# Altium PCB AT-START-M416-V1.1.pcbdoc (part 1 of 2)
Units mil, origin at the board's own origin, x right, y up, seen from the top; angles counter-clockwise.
Board outline 4292.45 x 3617.4 mil, 2 copper layers (Top Layer, Bottom Layer); 119 components, 108 nets, 464 pads, 671 vias.
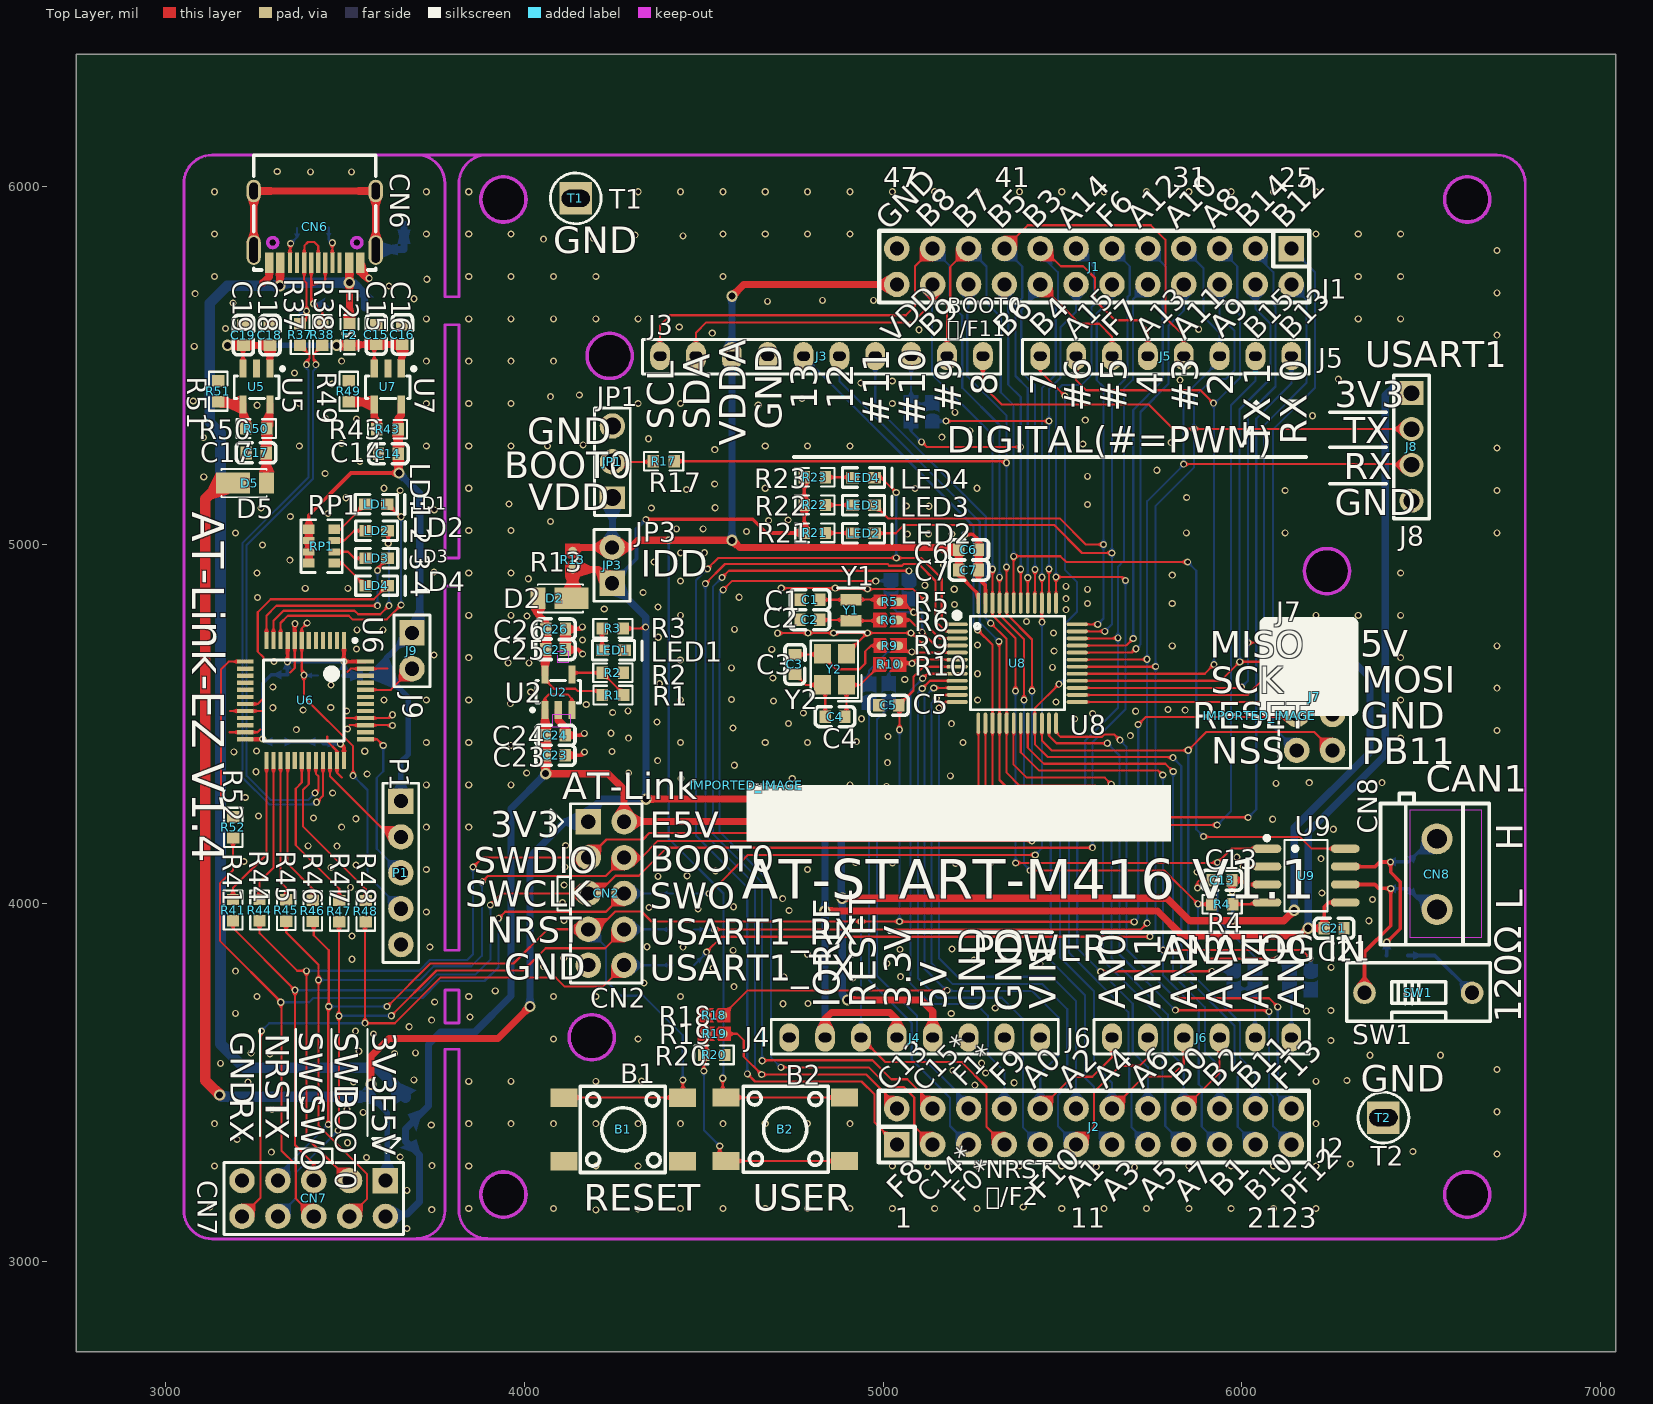
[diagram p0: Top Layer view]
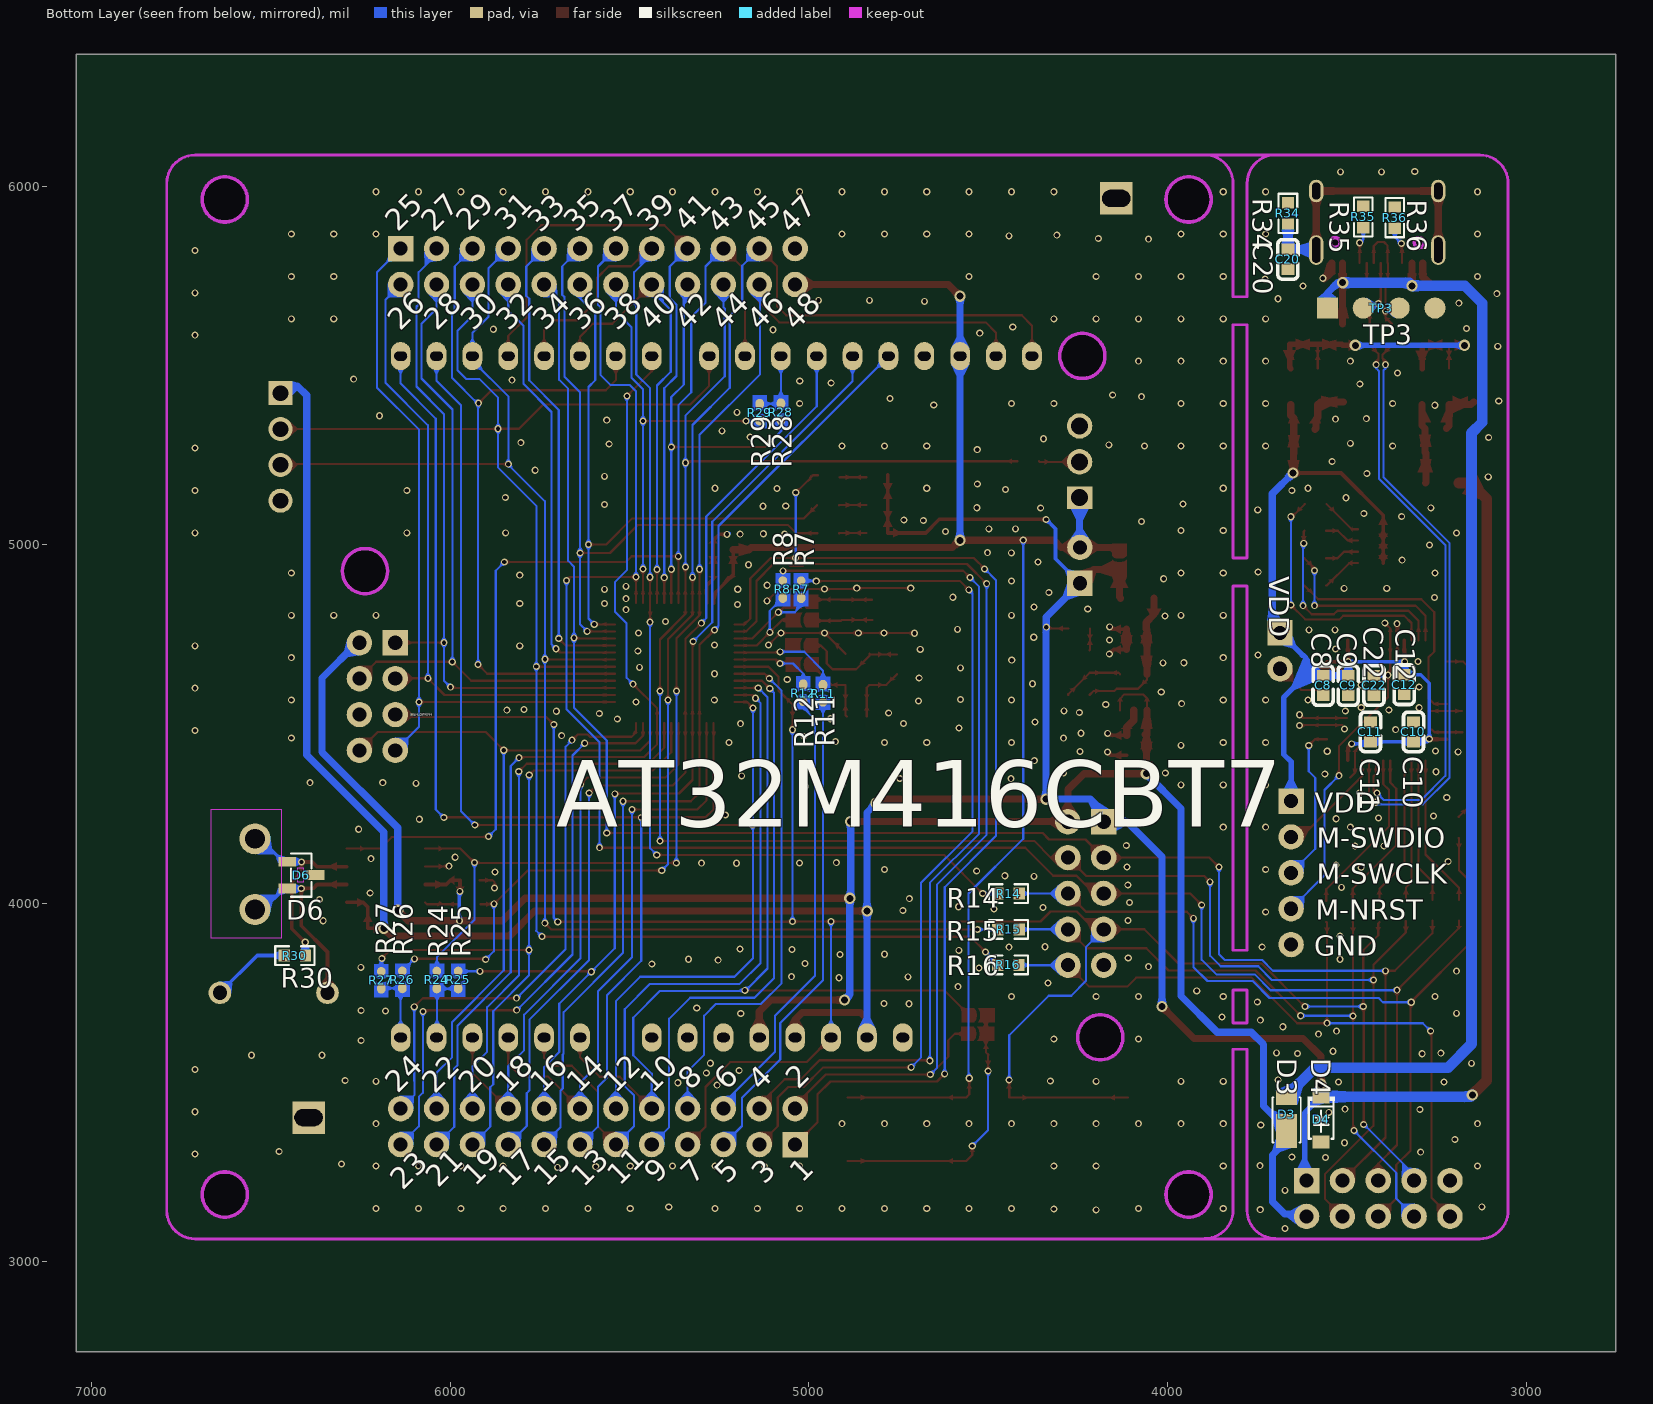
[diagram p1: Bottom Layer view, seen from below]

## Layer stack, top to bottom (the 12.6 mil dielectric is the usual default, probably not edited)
Top Layer: signal copper (thickness not stored)
Dielectric: dielectric 12.6, FR-4, Dk 4.8
Bottom Layer: signal copper (thickness not stored)

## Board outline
7042.45,2750 2750,2750 2750,6367.4 7042.45,6367.4
cut-out: 6691.34,5962.67 ccw(c6628.34,5962.67) 6565.35,5962.67 ccw(c6628.34,5962.67)
cut-out: 6691.34,3187.98 ccw(c6628.34,3187.98) 6565.35,3187.98 ccw(c6628.34,3187.98)
cut-out: 4003.92,3187.98 ccw(c3940.92,3187.98) 3877.93,3187.98 ccw(c3940.92,3187.98)
cut-out: 4250.26,3626.35 ccw(c4187.26,3626.35) 4124.27,3626.35 ccw(c4187.26,3626.35)
cut-out: 6300.26,4926.35 ccw(c6237.27,4925.79) 6174.28,4926.35 ccw(c6237.27,4926.91)
cut-out: 4300.26,5526.35 ccw(c4237.26,5526.35) 4174.27,5526.35 ccw(c4237.26,5526.35)
cut-out: 4003.93,5962.67 ccw(c3940.94,5962.44) 3877.95,5962.67 ccw(c3940.94,5962.89)

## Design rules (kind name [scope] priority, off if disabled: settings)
BoardOutlineClearance copperThickness1oz [All] p0: genericclearance=10 ignorepadtopadclearanceinfootprint=FALSE except(0: Arc-SplitContinuation Track-SplitContinuation SMDPad-SplitContinuation THPad-SplitContinuation Via-SplitContinuation Fill-SplitContinuation Poly-SplitContinuation Region-SplitContinuation Text-SplitContinuation; 6: SMDPad-CutoutEdge THPad-CutoutEdge Via-CutoutEdge Fill-CutoutEdge Region-CutoutEdge; 11.8: Track-OutlineEdge SMDPad-OutlineEdge THPad-OutlineEdge Via-OutlineEdge Fill-OutlineEdge Region-OutlineEdge Poly-OutlineEdge Text-OutlineEdge Track-CutoutEdge)
Clearance copperThickness1oz [(InNet('3V3') OR InNet('PA15') OR InNet('VCC') OR InNet('M-NRST') OR InNet('M-USB_DM') OR InNet('ATLINK_5V') OR InNet('M-USB_DP') OR InNet('USBP') OR InNet('USBM') OR InNet('GND') OR InNet('PB13') OR InNet('PC13') OR InNet('PB12') OR InNet('PB14') OR InNet('PB15') OR InNet('PB6') OR InNet('PB11') OR InNet('PB2') OR InNet('PB1') OR InNet('PF7') OR InNet('PF6') OR InNet('VDD') OR InNet('LD4') OR InNet('ATLK_RX') OR InNet('ATLK_TX') OR InNet('PF1') OR InNet('PF0') OR InNet('PC15') OR InNet('PC14') OR InNet('LD1') OR InNet('LD2') OR InNet('LD3') OR InNet('ATLK_SWCLK') OR InNet('ATLK_SWDIO') OR InNet('ATLK_BOOT0') OR InNet('ATLK_NRST') OR InNet('M-ATLK_TX') OR InNet('M-ATLK_RX') OR InNet('M-SWCLK') OR InNet('M-BOOT0') OR InNet('M-SWDIO') OR InNet('VCC3.5V') OR InNet('PA12') OR InNet('PA11') OR InNet('ATLK_SWO') OR InNet('$1N792') OR InNet('$1N793') OR InNet('$1N794') OR InNet('$1N795') OR InNet('$2N438') OR InNet('$3N526') OR InNet('$1N16959') OR InNet('PA14/SWCLK') OR InNet('PA13/SWDIO') OR InNet('PF11/BOOT0') OR InNet('NRST/PF2') OR InNet('PB3') OR InNet('$1N17598') OR InNet('$1N17675') OR InNet('$2N5975') OR InNet('$2N6210') OR InNet('$2N6248') OR InNet('$2N6104') OR InNet('$2N6111') OR InNet('$2N5937') OR InNet('$2N5955') OR InNet('$3N7356') OR InNet('$3N6624') OR InNet('$3N6989') OR InNet('$3N7005') OR InNet('$3N7010') OR InNet('$3N7265') OR InNet('PA0') OR InNet('$4N2984') OR InNet('$4N3391') OR InNet('$4N3469') OR InNet('PA6') OR InNet('E5V') OR InNet('PA9/USART1_TX') OR InNet('PA10/USART1_RX') OR InNet('PF8') OR InNet('PB10') OR InNet('PA8') OR InNet('PB4') OR InNet('PB5') OR InNet('PA2') OR InNet('PA3') OR InNet('PB0') OR InNet('PA4') OR InNet('PA1') OR InNet('PA5') OR InNet('PA7') OR InNet('PF10') OR InNet('PF9') OR InNet('PF12') OR InNet('PF13') OR InNet('CC2') OR InNet('CC1') OR InNet('EGND') OR InNet('$2N7510') OR InNet('SWO') OR InNet('CAN1_RX') OR InNet('CAN1_TX') OR InNet('CAN1_STB') OR InNet('CAN_L') OR InNet('CAN_H') OR InNet('$3N14088') OR InNet('$3N14090'))] p1: gap=7 ignorepadtopadclearanceinfootprint=FALSE except(6: Track-Track Track-SMDPad SMDPad-SMDPad Track-THPad SMDPad-THPad THPad-THPad Track-Via SMDPad-Via THPad-Via Via-Via Track-Fill SMDPad-Fill THPad-Fill Via-Fill Fill-Fill SMDPad-Region THPad-Region Via-Region Fill-Region Region-Region Track-Poly SMDPad-Poly THPad-Poly Via-Poly Fill-Poly Poly-Poly Track-Text SMDPad-Text THPad-Text Via-Text Fill-Text Region-Text Poly-Text Text-Text Track-Hole SMDPad-Hole THPad-Hole Via-Hole Fill-Hole Region-Hole Poly-Hole Text-Hole; 11.8: Track-Region Region-Poly Track-Sheet SMDPad-Sheet THPad-Sheet Via-Sheet Fill-Sheet Region-Sheet Poly-Sheet Text-Sheet Sheet-Hole)
DiffPairsRouting differentialPair [All] p1: maxuncoupledlength=10 minlimit=6 maxlimit=6 mostfreqgap=6 toplayer_minwidth=5 toplayer_prefwidth=10 toplayer_maxwidth=100 bottomlayer_minwidth=5 bottomlayer_prefwidth=10 bottomlayer_maxwidth=100
PasteMaskExpansion pasteMaskExpansion [All] p1: expansion=0
PlaneConnect innerPlane [All] p1: planeconnectstyle=Relief reliefexpansion=20 reliefentries=4 reliefconductorwidth=10 reliefairgap=10
PolygonConnect copperRegion [All] p1: connectstyle=Relief reliefentries=4 reliefconductorwidth=10 polygonreliefangle="90 Angle" airgapwidth=10
RoutingVias viaSize [All] p1: viastyle="Through Hole" holewidth=11.8 minholewidth=11.8 maxholewidth=27.6 width=19.7 minwidth=19.7 maxwidth=39.4
SolderMaskExpansion solderMaskExpansion [All] p1: useseparateexpansions=TRUE expansion=2 expansionbottom=2
Width copperThickness1oz [All] p1: maxlimit=100 minlimit=5 preferedwidth=6

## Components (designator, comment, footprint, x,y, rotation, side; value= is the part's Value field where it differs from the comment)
B1 "TS-1002S-05026C" KEY-SMD_4P-L6.0-W6.0-P4.50-LS9.0 4275.36,3369.64 r0 top
B2 "TSA063G60-250" KEY-SMD_4P-L6.1-W6.1-P4.50-LS9.0 4726.55,3369.99 r180 top
C1 "CL10C180JB8NNNC" C0603 4796.08,4846.54 r0 top
C2 "CL10C180JB8NNNC" C0603 4795.58,4790.46 r0 top
C3 "CL10C150JB8NNNC" C0603 4753.97,4666.49 r90 top
C4 "CL10C150JB8NNNC" C0603 4865.97,4520.49 r0 top
C5 "CC0603KRX7R9BB104" C0603 5015.49,4552.03 r0 top
C6 "CL10A475KO8NNNC" C0603 5238.29,4985.83 r180 top
C7 "CC0603KRX7R9BB104" C0603 5238.35,4929.24 r180 top
C8 "CL10A475KO8NNNC" C0603 3565.92,4607.82 r90 bottom
C9 "CC0603KRX7R9BB104" C0603 3495.92,4607.82 r90 bottom
C10 "CC0603KRX7R9BB104" C0603 3313.92,4477.82 r270 bottom
C11 "CC0603KRX7R9BB104" C0603 3433.92,4477.82 r270 bottom
C12 "CC0603KRX7R9BB104" C0603 3339.92,4609.82 r90 bottom
C13 "CC0603KRX7R9BB104" C0603 5944.97,4064.49 r0 top
C14 "CL10A106KP8NNNC" C0603 3620.53,5253.61 r0 top
C15 "CL10A106KP8NNNC" C0603 3586.1,5585.92 r270 top
C16 "CC0603KRX7R9BB104" C0603 3659.3,5585.96 r270 top
C17 "CL10A106KP8NNNC" C0603 3251.92,5255.82 r0 top
C18 "CL10A106KP8NNNC" C0603 3290.1,5583.92 r270 top
C19 "CC0603KRX7R9BB104" C0603 3216.1,5583.92 r270 top
C20 "CC0603KRX7R9BB104" C0603 3663.92,5795.82 r90 bottom
C21 "CC0603KRX7R9BB104" C0603 6256.97,3930.49 r180 top
C22 "CC0603KRX7R9BB104" C0603 3423.92,4607.82 r90 bottom
C23 "CL10A106KP8NNNC" C0603 4085.97,4412.49 r0 top
C24 "CC0603KRX7R9BB104" C0603 4085.97,4468.49 r0 top
C25 "CL10A106KP8NNNC" C0603 4086.25,4707.66 r0 top
C26 "CC0603KRX7R9BB104" C0603 4086.58,4764.74 r0 top
CN2 "CON10" HDR2X5 4177.67,4227.53 r270 top
CN6 "TYPEC-304-BCP16" USB-C-SMD_TYPEC-304-BCP16 3414.92,5885.82 r180 top
CN7 "CON10" HDR2X5 3612.1,3227.03 r180 top
CN8 "KF301-5.0-2P" CONN-TH_P5.00_KF301-5.0-2P 6543.97,4081.49 r90 top
D2 "DFLS130L-7" POWERDI-123_L2.8-W1.8-LS3.7-RD 4083.97,4850.49 r180 top
D3 "DFLS130L-7" POWERDI-123_L2.8-W1.8-LS3.7-RD 3667.92,3411.82 r90 bottom
D4 "SMF3.3A_C2759873" SOD-123FL_L2.8-W1.8-LS3.8-RD 3571.62,3397.74 r270 bottom
D5 "DFLS130L-7" POWERDI-123_L2.8-W1.8-LS3.7-RD 3233.92,5171.82 r0 top
D6 "PESD2CANFD24V-TR" SOT-23-3_L2.9-W1.3-P1.90-LS2.4-BR 6414.97,4078.49 r0 bottom
F2 "BSMD0603-050-6V" F0603 3511.92,5585.82 r270 top
IMPORTED_IMAGE "IMPORTED_IMAGE" IMPORTED_IMAGE 6049.2,4522.45 r0 top
IMPORTED_IMAGE "IMPORTED_IMAGE" IMPORTED_IMAGE 4619.97,4329.49 r0 top
J1 "Header 12X2" HEAD2*12 6137.91,5825.49 r180 top
J2 "Header 12X2" HEAD2*12 5037.93,3327.39 r0 top
J3 "CON10" "HDR1X10 - 2#" 5277.93,5525.82 r180 top
J4 "CON8" "HDR1X8 - 2#" 4737.93,3625.82 r0 top
J5 "CON8" "HDR1X8 - 2#" 6137.93,5525.82 r180 top
J6 "CON6" "HDR1X6 -2#" 5637.93,3625.82 r0 top
J7 "Header 4X2" HDR2X4 6152.93,4726.39 r270 top
J8 "PZ2.54-1*4-WZ" HDR-TH_4P-P2.54-H-M-W7.7-P 6473.03,5272.49 r270 top
J9 "1X2P_2.54M" HDR1X2 3686.1,4754.03 r270 top
JP1 "2.54-1*3P针" HDR-TH_3P-P2.54-V-M-1 4244.82,5230.95 r90 top
JP3 "1X2P_2.54M" HDR1X2 4243.97,4892.49 r90 top
LD1 "RED" LED0603 3556.14,5112.82 r0 top
LD2 "GREEN" LED0603 3557.1,5038.72 r0 top
LD3 "BLUE" LED0603 3557.14,4961.82 r0 top
LD4 "YELLOW" LED0603 3557.1,4885.82 r0 top
LED1 "RED" LED0603 4217.22,4705.31 r0 top
LED2 "RED" LED0603 4914.8,5031.55 r0 top
LED3 "YELLOW" LED0603 4914.43,5109.54 r0 top
LED4 "GREEN" LED0603 4914.61,5187.03 r0 top
P1 "Header 5" HDR1X5 3655.1,4285.03 r270 top
R1 "0603WAF5102T5E" R0603 4246.78,4580.68 r0 top
R2 "0603WAF1502T5E" R0603 4246.14,4642.98 r0 top
R3 "0603WAF1001T5E" R0603 4245.97,4766.49 r0 top
R4 "0603WAF3300T5E" R0603 5944.97,3997.49 r0 top
R5 "0603WAF0000T5E" SB-PAD_2 5019.42,4841.02 r0 top
R6 "0603WAF0000T5E" SB-PAD_2 5018.84,4789.96 r0 top
R7 "SB_PAD" SB-PAD_2 5021.33,4873.81 r270 bottom
R8 "SB_PAD" SB-PAD_2 5072.35,4874.25 r270 bottom
R9 "0603WAF0000T5E" SB-PAD_2 5019.02,4718.48 r0 top
R10 "0603WAF0000T5E" SB-PAD_2 5018.49,4665.95 r0 top
R11 "SB_PAD" SB-PAD_2 4960.34,4586.25 r90 bottom
R12 "SB_PAD" SB-PAD_2 5015.44,4587.74 r90 bottom
R13 "0603WAF0000T5E" SB-PAD_2 4133.97,4956.49 r270 top
R14 "0603WAF4700T5E" R0603 4443.07,4026.98 r180 bottom
R15 "0603WAF4700T5E" R0603 4443.1,3927.07 r180 bottom
R16 "0603WAF4700T5E" R0603 4443.46,3828.11 r180 bottom
R17 "0603WAF3301T5E" R0603 4387.97,5232.49 r180 top
R18 "0603WAF0000T5E" SB-PAD_2 4527.17,3688.08 r180 top
R19 "SB_PAD" SB-PAD_2 4528.62,3636.15 r180 top
R20 "0603WAF1003T5E" R0603 4528.75,3577.36 r0 top
R21 "0603WAF1001T5E" R0603 4809.4,5032.65 r180 top
R22 "0603WAF1001T5E" R0603 4809.4,5110.65 r180 top
R23 "0603WAF1001T5E" R0603 4809.4,5188.14 r180 top
R24 "SB_PAD" SB-PAD_2 6036.99,3785.48 r270 bottom
R25 "0603WAF0000T5E" SB-PAD_2 5977.56,3785.51 r270 bottom
R26 "SB_PAD" SB-PAD_2 6133.09,3785.81 r270 bottom
R27 "0603WAF0000T5E" SB-PAD_2 6192.02,3784.58 r270 bottom
R28 "SB_PAD" SB-PAD_2 5077.61,5371.23 r90 bottom
R29 "0603WAF0000T5E" SB-PAD_2 5136.87,5370.02 r90 bottom
R30 "0603WAF1200T5E" R0603 6432.97,3854.49 r180 bottom
R34 "RC0603FR-071ML" R0603 3663.92,5923.82 r90 bottom
R35 "0603WAF5101T5E" R0603 3453.92,5913.82 r90 bottom
R36 "0603WAF5101T5E" R0603 3365.92,5911.82 r90 bottom
R37 "0603WAF0000T5E" R0603 3373.92,5585.82 r270 top
R38 "0603WAF0000T5E" R0603 3435.92,5585.82 r270 top
R41 "0603WAF330JT5E" R0603 3187.3,3981.07 r270 top
R43 "0603WAF4702T5E" R0603 3617.92,5321.82 r180 top
R44 "0603WAF330JT5E" R0603 3261.3,3981.07 r270 top
R45 "0603WAF330JT5E" R0603 3335.3,3980.07 r270 top
R46 "0603WAF330JT5E" R0603 3409.3,3979.07 r270 top
R47 "0603WAF330JT5E" R0603 3483.3,3978.07 r270 top
R48 "0603WAF330JT5E" R0603 3557.3,3978.07 r270 top
R49 "0603WAF1502T5E" R0603 3509.92,5427.82 r90 top
R50 "0603WAF5102T5E" R0603 3251.92,5323.82 r180 top
R51 "0603WAF1502T5E" R0603 3145.92,5427.82 r90 top
R52 "0603WAF330JT5E" R0603 3187.92,4211.82 r270 top
RP1 "4D03WGJ0102T5E" RES-ARRAY-SMD_0603-8P-L3.2-W1.6-BL 3433.92,4995.82 r270 top
SW1 "DSWB01LHGET" SW-TH_DSWB01LHGET 6491.97,3750.49 r90 top
T1 "Test point" TestPoint 4142.64,5965.57 r0 top
T2 "Test point" TestPoint 6394.79,3402.35 r0 top
TP3 "1X4P_2.54F" "HDR1X4 - TOP" 3553.92,5659.82 r0 bottom
U2 "RT9080N-08GJ5" SOT-23-5 4157,4603.45 r90 top
U5 "RT9080N-08GJ5" SOT-23-5 3189.92,5425.82 r270 top
U6 "AT32F403ACCT7" "LQFP48 - 2" 3496.84,4733.03 r270 top locked
U7 "RT9080N-08GJ5" SOT-23-5 3555.92,5425.82 r270 top
U8 "AT32M412CxT7" LQFP-48_L7.0-W7.0-P0.50-LS9.0-BL 5373.54,4669.59 r270 top locked
U9 "MCP2562FD-E/SN" SOIC-8_L4.9-W3.9-P1.27-LS6.0-BL 6178.97,4077.49 r270 top
Y1 "32.768KHz" "XTAL_SOP - FC-12M" 4910.33,4846.79 r270 top
Y2 "CJ13-080001210B20" CRYSTAL-SMD_4P-L3.2-W2.5-BL 4863.97,4652.49 r90 top

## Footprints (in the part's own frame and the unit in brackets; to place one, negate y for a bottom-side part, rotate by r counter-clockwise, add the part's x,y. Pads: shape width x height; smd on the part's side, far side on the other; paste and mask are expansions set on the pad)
C0603 [mm]
  rect 0.8x0.9 smd: 1(-0.7,0) 2(0.7,0)
  silkscreen extent -1.41,-0.71 1.39,0.72
CONN-TH_P5.00_KF301-5.0-2P [mm]
  round 2.2 hole 1.4: 1(-2.5,0) 2(2.5,0)
  silkscreen extent -5,-3.7 5.71,4
CRYSTAL-SMD_4P-L3.2-W2.5-BL [mm]
  rect 1.4x1.2 smd: 1(-1.1,-0.85) 2(1.1,-0.85) 3(1.1,0.85) 4(-1.1,0.85)
  silkscreen extent -2.26,-1.91 2.03,1.68
F0603 [mil]
  rect 31.75x34.02 smd: 1(-29.66,0) 2(29.66,0)
  silkscreen extent -55,-25 55,25
HDR1X2 [mm]
  rect 1.8x1.8 hole 1: 1(0,0)
  round 1.8 hole 1: 2(2.54,0)
  silkscreen extent -1.27,-1.27 3.81,1.27
"HDR1X4 - TOP" [mm]
  rect 1.5x1.5 smd: 1(0,0)
  round 1.5 smd: 2(-2.54,0) 3(-5.08,0) 4(-7.62,0)
HDR1X5 [mm]
  rect 1.8x1.8 hole 1: 1(0,0)
  round 1.8 hole 1: 2(2.54,0) 3(5.08,0) 4(7.62,0) 5(10.16,0)
  silkscreen extent -1.27,-1.27 11.43,1.27
"HDR1X6 -2#" [mm]
  oval 1.4x2 hole 0.65 slot 0.9 at 0 deg: 1(0,0) 2(2.54,0) 3(5.08,0) 4(7.62,0) 5(10.16,0) 6(12.7,0)
  silkscreen extent -1.27,-1.17 13.97,1.27
"HDR1X8 - 2#" [mm]
  oval 1.4x2 hole 0.65 slot 0.9 at 0 deg: 1(0,0) 2(2.54,0) 3(5.08,0) 4(7.62,0) 5(10.16,0) 6(12.7,0) 7(15.24,0) 8(17.78,0)
  silkscreen extent -1.27,-1.17 19.05,1.27
"HDR1X10 - 2#" [mm]
  oval 1.4x2 hole 0.65 slot 0.9 at 0 deg: 1(0,0) 2(2.54,0) 3(5.08,0) 4(7.62,0) 5(10.16,0) 6(12.7,0) 7(15.24,0) 8(17.78,0) 9(20.32,0) 10(22.86,0)
  silkscreen extent -1.27,-1.17 24.1,1.27
HDR2X4 [mm]
  rect 1.8x1.8 hole 1: 1(0,0)
  round 1.8 hole 1: 2(0,2.54) 3(2.54,0) 4(2.54,2.54) 5(5.08,0) 6(5.08,2.54) 7(7.62,0) 8(7.62,2.54)
  silkscreen extent -1.27,-1.27 8.89,3.81
HDR2X5 [mm]
  rect 1.8x1.8 hole 1: 1(0,0)
  round 1.8 hole 1: 2(0,2.54) 3(2.54,0) 4(2.54,2.54) 5(5.08,0) 6(5.08,2.54) 7(7.62,0) 8(7.62,2.54) 9(10.16,0) 10(10.16,2.54)
  silkscreen extent -1.27,-1.27 11.43,3.81
HDR-TH_3P-P2.54-V-M-1 [mm]
  rect 1.575x1.8 hole 1.2: 1(-2.54,0)
  round 1.8 hole 1.2: 2(0,0) 3(2.54,0)
  silkscreen extent -3.81,-1.27 3.81,1.27
HDR-TH_4P-P2.54-H-M-W7.7-P [mm]
  rect 1.7x1.7 hole 1.1: 1(-3.81,0)
  round 1.7 hole 1.1: 2(-1.27,0) 3(1.27,0) 4(3.81,0)
  silkscreen extent -5.09,-1.27 5.09,1.27
HEAD2*12 [mm]
  rect 1.8x1.8 hole 1: 1(0,0)
  round 1.8 hole 1: 2(0,2.54) 3(2.54,0) 4(2.54,2.54) 5(5.08,0) 6(5.08,2.54) 7(7.62,0) 8(7.62,2.54) 9(10.16,0) 10(10.16,2.54) 11(12.7,0) 12(12.7,2.54) 13(15.24,0) 14(15.24,2.54) 15(17.78,0) 16(17.78,2.54) 17(20.32,0) 18(20.32,2.54) 19(22.86,0) 20(22.86,2.54) 21(25.4,0) 22(25.4,2.54) 23(27.94,0) 24(27.94,2.54)
  silkscreen extent -1.27,-1.27 29.19,3.81
IMPORTED_IMAGE [mil]
  silkscreen extent 0,0 276,276
KEY-SMD_4P-L6.0-W6.0-P4.50-LS9.0 [mm]
  rect 1.9x1.3 smd: 1(-4.2,2.25) 2(4.2,2.25) 3(-4.2,-2.25) 4(4.2,-2.25)
  silkscreen extent -3.05,-3.05 2.98,3.05
KEY-SMD_4P-L6.1-W6.1-P4.50-LS9.0 [mm]
  rect 1.9x1.3 smd: 1(-4.2,2.25) 2(4.2,2.25) 3(-4.2,-2.25) 4(4.2,-2.25)
  silkscreen extent -3.05,-3.05 2.98,3.05
LED0603 [mil]
  rect 36x32 smd: 1(-0.04,0.2) 2(60.96,0.2)
  silkscreen extent -28,-28 110,27
"LQFP48 - 2" [mm]
  rect 1.2x0.3 smd: 1(0,0) 2(0,-0.5) 3(0,-1) 4(0,-1.5) 5(0,-2) 6(0,-2.5) 7(0,-3) 8(0,-3.5) 9(0,-4) 10(0,-4.5) 11(0,-5) 12(0,-5.5) 25(8.5,-5.5) 26(8.5,-5) 27(8.5,-4.5) 28(8.5,-4) 29(8.5,-3.5) 30(8.5,-3) 31(8.5,-2.5) 32(8.5,-2) 33(8.5,-1.5) 34(8.5,-1) 35(8.5,-0.5) 36(8.5,0)
  rect 0.3x1.2 smd: 13(1.5,-7) 14(2,-7) 15(2.5,-7) 16(3,-7) 17(3.5,-7) 18(4,-7) 19(4.5,-7) 20(5,-7) 21(5.5,-7) 22(6,-7) 23(6.5,-7) 24(7,-7) 37(7,1.5) 38(6.5,1.5) 39(6,1.5) 40(5.5,1.5) 41(5,1.5) 42(4.5,1.5) 43(4,1.5) 44(3.5,1.5) 45(3,1.5) 46(2.5,1.5) 47(2,1.5) 48(1.5,1.5)
  silkscreen extent -0.12,-5.71 7.11,0.89
LQFP-48_L7.0-W7.0-P0.50-LS9.0-BL [mil]
  oval 10.6x59.1 smd: 1(-108.3,-167.3) 2(-88.6,-167.3) 3(-68.9,-167.3) 4(-49.2,-167.3) 5(-29.5,-167.3) 6(-9.8,-167.3) 7(9.8,-167.3) 8(29.5,-167.3) 9(49.2,-167.3) 10(68.9,-167.3) 11(88.6,-167.3) 12(108.3,-167.3) 25(108.3,167.3) 26(88.6,167.3) 27(68.9,167.3) 28(49.2,167.3) 29(29.5,167.3) 30(9.8,167.3) 31(-9.8,167.3) 32(-29.5,167.3) 33(-49.2,167.3) 34(-68.9,167.3) 35(-88.6,167.3) 36(-108.3,167.3)
  oval 59.1x10.6 smd: 13(167.3,-108.3) 14(167.3,-88.6) 15(167.3,-68.9) 16(167.3,-49.2) 17(167.3,-29.5) 18(167.3,-9.8) 19(167.3,9.8) 20(167.3,29.5) 21(167.3,49.2) 22(167.3,68.9) 23(167.3,88.6) 24(167.3,108.3) 37(-167.3,108.3) 38(-167.3,88.6) 39(-167.3,68.9) 40(-167.3,49.2) 41(-167.3,29.5) 42(-167.3,9.8) 43(-167.3,-9.8) 44(-167.3,-29.5) 45(-167.3,-49.2) 46(-167.3,-68.9) 47(-167.3,-88.6) 48(-167.3,-108.3)
  silkscreen extent -141,-176 130,132
POWERDI-123_L2.8-W1.8-LS3.7-RD [mm]
  rect 2.4x1.5 smd: 1(-1.187,0)
  rect 1.05x1.5 smd: 2(1.187,0)
  silkscreen extent -2,-1 1.2,1
R0603 [mil]
  rect 31.75x34.02 smd: 1(-29.66,0) 2(29.66,0)
  silkscreen extent -55,-26 55,26
RES-ARRAY-SMD_0603-8P-L3.2-W1.6-BL [mm]
  rect 0.65x0.8 smd: 1(-1.2,-0.9) 4(1.2,-0.9) 5(1.2,0.9) 8(-1.2,0.9)
  rect 0.5x0.8 smd: 2(-0.4,-0.9) 3(0.4,-0.9) 6(0.4,0.9) 7(-0.4,0.9)
  silkscreen extent -1.87,-1.45 1.87,1.47
SB-PAD_2 [mil]
  oval 24.6x24 smd: 1(-25.5,0)
  oval 28.2x24 smd: 2(22.5,0)
  Top Layer region: -46,20 -12,20 -6.82,12.19 -5,3 -5,3 -5,-3 -6.82,-12.19 -12,-20 -12,-20 -46,-20
  Top Layer region: -1,20 3.47,12.03 5.01,3.03 5.01,3.02 5.01,-2.98 3.47,-12.01 -1,-20 -1,-20 46,-20 46,20
SOD-123FL_L2.8-W1.8-LS3.8-RD [mm]
  rect 0.93x1.2 smd: 1(-1.6,0) 2(1.6,0)
  silkscreen extent -1.6,-0.95 1.38,0.95
SOIC-8_L4.9-W3.9-P1.27-LS6.0-BL [mm]
  oval 0.588x2.045 smd: 1(-1.905,-2.772) 2(-0.635,-2.772) 3(0.635,-2.772) 4(1.905,-2.772) 5(1.905,2.772) 6(0.635,2.772) 7(-0.635,2.772) 8(-1.905,2.772)
  silkscreen extent -2.8,-2.92 2.53,1.52
SOT-23-3_L2.9-W1.3-P1.90-LS2.4-BR [mm]
  rect 1.25x0.7 smd: 1(1,-0.95) 2(1,0.95) 3(-1,0)
  silkscreen extent -0.73,-1.53 0.73,1.53
SOT-23-5 [mil]
  rect 50x20 smd: 1(-65,100) 2(-65,63) 3(-65,25) 4(35,25) 5(35,100)
  silkscreen extent -65,1 18,135
SW-TH_DSWB01LHGET [mm]
  round 1.6 hole 1: 1(0,3.81) 2(0,-3.81)
  silkscreen extent -2.02,-5.11 2.13,5.05
TestPoint [mm]
  rect 2.3x2.3 hole 1.2 slot 2 at 0 deg: 1(0,0)
  silkscreen extent -1.8,-1.8 1.8,1.8
USB-C-SMD_TYPEC-304-BCP16 [mil]
  oval 39.4x82.7 hole 23.6 slot 70.9 at 90 deg: 13(-170.1,64.3) 14(170.1,64.3)
  oval 39.4x63 hole 23.6 slot 47.2 at 90 deg: 15(-170.1,-100.3) 16(170.1,-100.3)
  rect 23.6x57.1 smd: A1B12(-127,100.3) A4B9(-96.5,100.3) B1A12(126.8,100.3) B4A9(96.5,100.3)
  rect 11.8x57.1 smd: A5(-49.2,100.3) A6(-9.8,100.3) A7(9.8,100.3) A8(49.2,100.3) B5(68.9,100.3) B6(29.5,100.3) B7(-29.5,100.3) B8(-68.9,100.3)
  Board Outline Layer circle w0.2: c117.3,43.4 r13.8
  Board Outline Layer circle w0.2: c-117.3,43.4 r13.8
  Board Outline Layer circle w10: c117.3,43.4 r13.8
  Board Outline Layer circle w10: c-117.3,43.4 r13.8
  Multi-Layer board cut-out: 103.5,43.4 105.35,36.5 110.4,31.45 117.3,29.6 124.2,31.45 129.26,36.5 131.1,43.4 131.1,43.4 129.74,49.39 125.91,54.19 120.37,56.86 114.23,56.86 108.7,54.19 104.87,49.39 103.5,43.4
  Multi-Layer board cut-out: -131.1,43.4 -129.25,36.5 -124.2,31.45 -117.3,29.6 -110.4,31.45 -105.34,36.5 -103.5,43.4 -103.5,43.4 -104.86,49.39 -108.69,54.19 -114.23,56.86 -120.37,56.86 -125.9,54.19 -129.73,49.39 -131.1,43.4
  silkscreen extent -170,-200 170,120
"XTAL_SOP - FC-12M" [mm]
  rect 0.8x1.5 smd: 1(0,0) 2(1.5,0)
  silkscreen extent -0.81,-0.99 2.29,0.94

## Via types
v1: diameter 19.68, hole 11.81, Top Layer to Bottom Layer, 317 vias
v2: diameter 19.7, hole 11.81, Top Layer to Bottom Layer, 224 vias
v3: diameter 19.7, hole 11.8, Top Layer to Bottom Layer, 111 vias
v4: diameter 31.5, hole 19.68, Top Layer to Bottom Layer, 19 vias

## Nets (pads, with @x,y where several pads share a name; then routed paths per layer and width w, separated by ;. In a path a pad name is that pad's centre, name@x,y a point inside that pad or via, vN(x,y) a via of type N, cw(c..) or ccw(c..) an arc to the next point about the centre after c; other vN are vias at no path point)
3V3: C21.2 CN2.1 CN7.1 D2.1 D4.1 D5.1 J4.2 J4.4 J8.1 JP3.1 R3.2 R13.2 R21.2 R22.2 R23.2 U9.5 | length 10323.8
  Top Layer w6: R3.2@4275.63,4766.49 4334.18,4766.49 v1(4337.78,4770.08)
  Top Layer w10: v3(4337.97,5070.49) 4635.97,5070.49 4673.81,5032.65 R21.2@4779.74,5032.65 R22.2@4779.74,5110.65 R23.2@4779.74,5194.65 ; v4(6184.97,3930.49) C21.2@6229.41,3930.49 6229.41,3989.93 6241.97,4002.49 U9.5@6288.12,4002.49
  Top Layer w20: v4(3571.92,3495.39) 3571.92,3573.75 3621.61,3623.44 3926.07,3623.44 v4(4015.07,3712.44) ; D2.1@4130.72,4850.49 4133.97,4853.74 R13.2@4133.97,4933.99 4137.47,4930.49 4205.97,4930.49 JP3.1@4243.97,4892.49 ; v4(4338.67,4290.58) 4800.53,4290.58 v4(4812.37,4278.74) ; v4@4837.24,3978.49 5764.97,3978.49 5834.97,3908.49 6162.97,3908.49 v4(6184.97,3930.49) ; J4.2@4837.93,3625.82 4837.93,3678.13 4855.64,3695.85 5018.49,3695.85 5037.93,3676.41 J4.4@5037.93,3625.82
  Top Layer w30: v4(3149.92,3465.82) 3109.62,3506.12 3109.62,5127.51 3153.92,5171.82 D5.1@3187.17,5171.82
  Bottom Layer w10: JP3.1@4243.97,4892.49 4311.97,4960.49 4311.97,5044.49 v3(4337.97,5070.49)
  Bottom Layer w15: D4.1@3571.62,3460.73 3617.4,3414.95 3617.4,3232.32 CN7.1@3612.1,3227.03
  Bottom Layer w20: D4.1@3571.62,3460.73 3571.92,3461.03 v4(3571.92,3495.39) ; v4(4015.07,3712.44) 4015.07,4129.63 4112.97,4227.53 CN2.1@4177.67,4227.53 4177.67,4253.94 4214.31,4290.58 v4(4338.67,4290.58) 4338.67,4769.19 v1(4337.78,4770.08) 4337.78,4798.68 JP3.1@4243.97,4892.49 ; v4(4812.37,4278.74) 4837.93,4253.18 4837.93,4047.53 4837.52,4047.12 4837.52,3626.23 J4.2@4837.93,3625.82 ; v4(6184.97,3930.49) 6184.97,4198.49 6399.97,4413.49 6399.97,5416.49 6425.36,5441.87 6453.64,5441.87 J8.1@6473.03,5422.49
  Bottom Layer w30: v4(3149.92,3465.82) 3155.01,3460.73 D4.1@3571.62,3460.73
  other v4: 4837.19,3978.44
$1N792: LD1.1 RP1.8 | length 115.7
  Top Layer w6: RP1.8@3469.36,5043.06 3486.13,5043.06 LD1.1@3556.1,5113.03
$1N793: LD2.1 RP1.7 | length 99
  Top Layer w6: RP1.7@3469.36,5011.57 3497.67,5011.57 3525.04,5038.93 LD2.1@3557.06,5038.93
$1N794: LD3.1 RP1.6 | length 95.2
  Top Layer w6: RP1.6@3469.36,4980.07 3507.67,4980.07 3525.72,4962.03 LD3.1@3557.1,4962.03
$1N795: LD4.1 RP1.5 | length 113.6
  Top Layer w6: RP1.5@3469.36,4948.58 3493.16,4948.58 3555.72,4886.03 LD4.1@3557.06,4886.03
$1N16959: C15.2 C16.2 C18.2 C19.2 F2.2 U5.1 U5.3 U7.1 U7.3 | length 876.6
  Top Layer w6: U5.3@3214.92,5490.82 3214.92,5555.18 C19.2@3215.56,5555.82 ; U7.3@3580.92,5490.82 3580.92,5553.18 C15.2@3586.1,5558.36
  Top Layer w15: v4(3171.92,5555.82) C19.2@3215.56,5555.82 ; C19.2@3216.1,5556.36 C19.2@3215.56,5555.82 ; U5.1@3289.92,5490.82 3289.92,5555.46 C18.2@3289.56,5555.82 ; C18.2@3290.1,5556.36 C18.2@3289.56,5555.82 ; v4(3475.92,5555.82) 3476.26,5556.16 F2.2@3511.92,5556.16 3514.12,5558.36 C15.2@3586.1,5558.36 C16.2@3659.3,5558.4 ; U7.1@3655.92,5490.82 3659.3,5494.2 C16.2@3659.3,5558.4 ; C19.2@3215.56,5555.82 C18.2@3289.56,5555.82
  Bottom Layer w15: v4(3171.92,5555.82) v4(3475.92,5555.82)
$1N17598: R43.2 R49.1 U7.4 | length 146.1
  Top Layer w20: R49.1@3509.92,5398.16 3573.58,5398.16 U7.4@3580.92,5390.82 3580.92,5354.82 3585.92,5349.82 3585.92,5324.16 R43.2@3588.26,5321.82
$1N17675: R50.2 R51.1 U5.4 | length 142.1
  Top Layer w20: R51.1@3145.92,5398.16 3153.26,5390.82 U5.4@3214.92,5390.82 3214.92,5331.16 R50.2@3222.26,5323.82
$2N438: C2.2 R6.1 Y1.2 | length 172.2
  Top Layer w6: C2.2@4823.14,4790.46 4907.6,4790.46 Y1.2@4910.33,4787.73 4991.11,4787.73 R6.1@4993.34,4789.96
$2N5937: R9.2 R11.2 U8.5 | length 354.5
  Top Layer w6: R9.2@5041.52,4718.48 5041.52,4717.83 5058.08,4701.27 v2(5079.84,4701.27) 5082.01,4699.09 U8.5@5206.24,4699.09
  Bottom Layer w6: R11.2@4960.34,4608.75 4960.34,4648.92 5012.69,4701.27 v2(5079.84,4701.27)
$2N5955: R10.2 R12.2 U8.6 | length 278.6
  Top Layer w6: R10.2@5040.99,4665.95 5045.31,4670.27 5078.72,4670.27 v2(5080.18,4668.81) 5090.76,4679.39 U8.6@5206.24,4679.39
  Bottom Layer w6: R12.2@5015.44,4610.24 5015.44,4640.29 5043.96,4668.81 v2(5080.18,4668.81)
$2N5975: C1.2 R5.1 Y1.1 | length 172.8
  Top Layer w6: C1.2@4823.64,4846.54 4910.08,4846.54 Y1.1@4910.33,4846.79 4988.15,4846.79 R5.1@4993.92,4841.02
$2N6104: R5.2 R7.2 U8.3 | length 299.5
  Top Layer w6: R5.2@5041.92,4841.02 5055.32,4841.02 v2(5084.81,4811.52) 5157.84,4738.49 U8.3@5206.24,4738.49
  Bottom Layer w6: R7.2@5021.33,4851.31 5021.33,4829.49 5039.29,4811.52 v2(5084.81,4811.52)
$2N6111: R6.2 R8.2 U8.4 | length 305.7
  Top Layer w6: R6.2@5041.34,4789.96 5074.21,4789.96 v2(5108.68,4755.5) 5145.38,4718.79 U8.4@5206.24,4718.79
  Bottom Layer w6: R8.2@5072.35,4851.75 5108.72,4815.38 v2(5108.68,4755.5)
$2N6210: C3.2 R9.1 Y2.3 | length 308.9
  Top Layer w6: C3.2@4753.97,4694.05 4828.76,4694.05 Y2.3@4830.51,4695.8 4830.51,4689.95 4867.97,4652.49 4933.97,4652.49 4949.97,4668.49 4949.97,4702.49 4965.96,4718.48 R9.1@4993.52,4718.48
$2N6248: C4.2 R10.1 Y2.1 | length 209.4
  Top Layer w6: C4.2@4893.53,4520.49 4897.44,4524.39 Y2.1@4897.44,4609.18 4936.22,4609.18 R10.1@4992.99,4665.95
$2N7510: JP1.2 R17.2 | length 114.1
  Top Layer w6: JP1.2@4244.82,5230.95 4356.77,5230.95 R17.2@4358.31,5232.49
$3N526: LED1.1 R3.1 | length 61.3
  Top Layer w6: R3.1@4216.31,4766.49 4216.31,4706.38 LED1.1@4217.18,4705.52
$3N6624: C25.1 C26.1 D2.2 R1.1 U2.5 | length 414.7
  Top Layer w6: U2.5@4057,4638.45 4057,4623.46 4081.97,4598.49 4141.52,4598.49 4147.52,4592.49 4205.31,4592.49 R1.1@4217.12,4580.68
  Top Layer w20: D2.2@4037.22,4850.49 4037.22,4805.24 4059.02,4783.43 C26.1@4059.02,4764.74 4057,4762.71 U2.5@4057,4638.45
$3N6989: LED2.1 R21.1 | length 76.3
  Top Layer w6: R21.1@4839.06,5032.65 4914.12,5032.65 LED2.1@4915.02,5031.75
$3N7005: LED3.1 R22.1 | length 77.5
  Top Layer w6: R22.1@4839.06,5110.65 4915.27,5110.65 LED3.1@4916.17,5109.75
$3N7010: LED4.1 R23.1 | length 75.5
  Top Layer w6: R23.1@4839.06,5188.14 4913.27,5188.14 LED4.1@4914.17,5187.24
$3N7265: R1.2 R2.1 U2.4 | length 173.5
  Top Layer w6: U2.4@4132,4638.45 4136.52,4642.98 R2.1@4216.48,4642.98 4276.44,4583.03 R1.2@4276.44,4580.68
$3N7356: B2.1 B2.2 R18.2 R19.2 R20.1 | length 766.6
  Top Layer w6: v3(4499.91,3532.38) 4499.91,3576.55 R20.1@4499.09,3577.36 4506.12,3584.4 R19.2@4506.12,3636.15 4506.12,3686.62 R18.2@4504.67,3688.08 ; v3(4544.29,3323.42) 4544.29,3298.32 B2.2@4561.2,3281.41 B2.1@4891.91,3281.41
  Bottom Layer w6: v3(4499.91,3532.38) 4499.91,3367.8 v3(4544.29,3323.42)
$3N14088: R4.2 U9.4 | length 97.3
  Top Layer w6: R4.2@5974.63,3997.49 6064.82,3997.49 U9.4@6069.82,4002.49
$3N14090: R30.1 SW1.2 | length 222.4
  Bottom Layer w10: R30.1@6462.63,3854.49 6537.97,3854.49 SW1.2@6641.97,3750.49
$4N2984: J6.5 R24.2 R25.2 | length 197.2
  Bottom Layer w6: R25.2@5977.56,3763.01 5978.33,3762.24 R24.2@6036.25,3762.24 ; R24.2@6036.99,3762.98 R24.2@6036.25,3762.24 ; J6.5@6037.93,3625.82 6036.25,3627.49 R24.2@6036.25,3762.24
$4N3391: J6.6 R26.2 R27.2 | length 198.9
  Bottom Layer w6: J6.6@6137.93,3625.82 6137.93,3758.47 R26.2@6133.09,3763.31 6190.8,3763.31 R27.2@6192.02,3762.08
$4N3469: J3.3 R28.2 R29.2 | length 194.5
  Bottom Layer w6: R28.2@5077.61,5393.73 5077.93,5394.05 R28.2@5077.93,5400.54 ; J3.3@5077.93,5525.82 R28.2@5077.93,5400.54 ; R29.2@5136.87,5392.52 5085.95,5392.52 R28.2@5077.93,5400.54
ATLINK_5V: CN6.A4B9 CN6.B4A9 D3.2 F2.1 TP3.1 | length 3402
  Top Layer w20: v4(3317.92,5721.82) 3318.42,5722.32 CN6.B4A9@3318.42,5785.52 ; CN6.A4B9@3511.42,5785.52 v4(3511.42,5730.45) 3511.42,5615.98 F2.1@3511.92,5615.48
  Bottom Layer w20: v4@3317.77,5722.16 3317.77,5721.98 v4(3317.92,5721.82) ; v4(3511.42,5730.45) 3525.3,5730.45 3553.92,5701.82 TP3.1@3553.92,5659.82
  Bottom Layer w30: v4(3511.42,5730.45) 3326.05,5730.45 3317.77,5722.16 3171.08,5722.16 3121.92,5673 3121.92,5341.67 3151.92,5311.67 3151.92,3607.82 3217.92,3541.82 3588.66,3541.82 3667.92,3462.56 D3.2@3667.92,3458.57
ATLK_BOOT0: R45.1 U6.27 | length 395.7
  Top Layer w6: U6.27@3319.67,4398.38 3319.67,4059.15 3335.1,4043.72 R45.1@3335.1,4009.03
ATLK_NRST: R46.1 U6.28 | length 419.2
  Top Layer w6: U6.28@3339.36,4398.38 3339.36,4109.89 3409.1,4040.15 R46.1@3409.1,4008.03
ATLK_RX: CN2.10 CN7.10 R16.2 R48.2 | length 2067.5
  Top Layer w6: CN7.10@3212.1,3127.03 3263.92,3178.85 3263.92,3641.82 v1(3265.92,3643.82) ; v2@3555.24,3665.79 3555.24,3946.34 R48.2@3557.3,3948.41 ; v2(3555.29,3665.74) 3638.2,3665.74 3765.32,3792.85 4087.09,3792.85 4112.1,3767.84 4217.99,3767.84 CN2.10@4277.67,3827.53
  Bottom Layer w6: v1(3265.92,3643.82) 3287.84,3665.74 v2(3555.29,3665.74) ; CN2.10@4277.67,3827.53 4413.22,3827.53 R16.2@4413.8,3828.11
ATLK_SWCLK: R41.1 U6.25 | length 427
  Top Layer w6: R41.1@3187.1,4010.03 3187.1,4042.99 3280.3,4136.2 U6.25@3280.3,4398.38
ATLK_SWDIO: R44.1 U6.26 | length 404.5
  Top Layer w6: R44.1@3261.1,4010.03 3261.1,4060.3 3299.99,4099.19 U6.26@3299.99,4398.38
ATLK_SWO: R52.1 U6.13 | length 502.2
  Top Layer w6: R52.1@3187.92,4241.48 3153.1,4276.31 3153.1,4652.04 3175.02,4673.97 U6.13@3221.25,4673.97
ATLK_TX: CN2.8 CN7.8 R15.2 R47.2 | length 1923.7
  Top Layer w6: v2(3480.15,3366.52) 3482.31,3368.67 v2(3482.31,3686.03) 3482.31,3947.41 R47.2@3483.3,3948.41 ; v1(3628.47,3686.56) 3754.42,3812.52 3996.88,3812.52 4058.93,3874.57 4224.71,3874.57 CN2.8@4277.67,3927.53
  Bottom Layer w6: CN7.8@3312.1,3127.03 3362.1,3177.03 3362.1,3248.47 v2(3480.15,3366.52) ; v2(3482.31,3686.03) 3482.84,3686.56 v1(3628.47,3686.56) ; CN2.8@4277.67,3927.53 4388.57,3927.53 4389.03,3927.07 R15.2@4413.44,3927.07
CAN1_RX: J1.21 J3.10 R4.1 R26.1 U8.45 | length 3802
  Top Layer w6: J3.10@4377.93,5525.82 4377.93,5611.25 4406.23,5639.55 5063.23,5639.55 5088.64,5664.96 5088.64,5776.22 J1.21@5137.91,5825.49 ; v2(5324.34,4909.04) U8.45@5324.34,4836.89 5324.34,4804.29 5392.43,4736.19 v1(5392.43,4567.27) ; v3(5409.97,4091.49) 5783.97,4091.49 5877.97,3997.49 R4.1@5915.31,3997.49 ; v3(5900.97,3843.49) 5902.83,3845.35 v1(6099.34,3845.35)
  Bottom Layer w6: J1.21@5137.91,5825.49 5185.54,5777.86 5185.54,5673.33 5220.26,5638.61 5220.26,5437.7 5324.34,5333.62 v2(5324.34,4909.04) ; v1(5392.43,4567.27) 5392.43,4109.03 v3(5409.97,4091.49) ; v3(5877.97,3998.49) 5877.97,3866.49 v3(5900.97,3843.49) ; v1(6099.34,3845.35) 6133.09,3811.61 R26.1@6133.09,3811.31
CAN1_STB: J1.19 J3.2 U8.43 U9.8 | length 3049.6
  Top Layer w6: J3.2@5177.93,5525.82 5177.93,5664.32 5187.01,5673.4 5187.01,5774.59 J1.19@5237.91,5825.49 ; U8.43@5363.74,4836.89 v3(5363.74,4967.54) 5493.92,4967.54 5509.97,4951.49 v3(5848.97,4951.49) ; v3(5892.97,4186.49) 5894.97,4184.49 6162.97,4184.49 6194.97,4152.49 U9.8@6288.12,4152.49
  Bottom Layer w6: J1.19@5237.91,5825.49 5287.82,5775.59 5287.82,5674.47 5327.64,5634.65 5327.64,5424.76 5363.74,5388.66 v3(5363.74,4967.54) ; v3(5848.97,4951.49) 5872.97,4927.49 5872.97,4206.49 v3(5892.97,4186.49)
CAN1_TX: J1.22 J3.9 R24.1 U8.46 U9.1 | length 3583.2
  Top Layer w6: J3.9@4477.93,5525.82 4477.93,5591.17 4506.72,5619.96 5082.29,5619.96 5137.91,5675.58 J1.22@5137.91,5725.49 ; v2(5304.64,4931.39) U8.46@5304.64,4836.89 5304.64,4802.85 5368.76,4738.73 v1(5368.76,4591.97) ; v3(5369.42,4112.75) v3@5931.97,4112.75 ; v3(5931.97,4113.53) 5970.93,4152.49 U9.1@6069.82,4152.49
  Bottom Layer w6: J1.22@5137.91,5725.49 5135.73,5723.31 5135.73,5474.99 5304.64,5306.08 v2(5304.64,4931.39) ; v1(5368.76,4591.97) 5368.76,4113.41 v3(5369.42,4112.75) ; v3(5931.97,4113.53) 5931.97,3954.49 6036.99,3849.47 R24.1@6036.99,3810.98
CAN_H: CN8.2 D6.1 R30.2 U9.7 | length 575.9
  Top Layer w10: U9.7@6288.12,4102.49 6372.16,4102.49 6384.81,4115.14 v3(6414.69,4115.14) 6414.69,4086.76 6441.97,4059.49 6441.97,3929.49 v3(6403.97,3891.49)
  Bottom Layer w10: R30.2@6403.31,3854.49 6403.97,3855.15 v3(6403.97,3891.49) ; v3(6414.69,4115.14) 6415.45,4115.89 6465.37,4115.89 6529.4,4179.91 CN8.2@6543.97,4179.91
CAN_L: CN8.1 D6.2 SW1.1 U9.6 | length 605.9
  Top Layer w10: U9.6@6288.12,4052.49 6371.02,4052.49 6382.02,4041.49 v3(6415.1,4041.49) 6415.1,3937.62 6341.97,3864.49 SW1.1@6341.97,3750.49
  Bottom Layer w10: v3(6415.1,4041.49) 6415.5,4041.09 6463.37,4041.09 6521.4,3983.06 CN8.1@6543.97,3983.06
CC1: CN6.A5 R35.1 | length 102.9
  Top Layer w6: v1(3463.92,5841.82) 3464.12,5841.62 CN6.A5@3464.12,5785.52
  Bottom Layer w6: R35.1@3453.92,5884.16 3453.92,5851.82 v1(3463.92,5841.82)
CC2: CN6.B5 R36.1 | length 104.9
  Top Layer w6: CN6.B5@3346.02,5785.52 3346.02,5837.92 v1(3347.92,5839.82)
  Bottom Layer w6: v1(3347.92,5839.82) 3365.92,5857.82 R36.1@3365.92,5882.16
E5V: C13.2 C23.1 C24.1 CN2.2 CN7.2 D3.1 J4.5 J7.2 U2.1 U2.3 U9.3 | length 6030.8
  Top Layer w6: U2.1@4057,4538.45 4057,4571.51 4067.97,4582.49 4119.97,4582.49 4132,4570.46 U2.3@4132,4538.45
  Top Layer w10: v3(5972.97,4033.49) 5971.97,4034.49 5972.53,4035.05 C13.2@5972.53,4064.49 5998.97,4064.49 6010.97,4052.49 U9.3@6069.82,4052.49
  Top Layer w20: U2.1@4057,4538.45 4057,4469.9 C24.1@4058.41,4468.49 ; v4(4883.12,4228.41) 4278.55,4228.41 CN2.2@4277.67,4227.53 4277.67,4316.56 4232.8,4361.43 v4(4058.75,4361.43) 4058.41,4361.77 C23.1@4058.41,4412.49 C24.1@4058.41,4468.49 ; v4(4885.6,4014.04) 5791.42,4014.04 5853.97,3951.49 v3(5974.12,3951.49) 6116.97,3951.49 v4(6145.97,3980.49) ; v4(4900.59,3730.66) 5105.75,3730.66 5137.93,3698.49 J4.5@5137.93,3625.82 ; C24.1@4058.41,4468.49 4060.6,4470.68 4062.22,4470.68 4060.04,4468.49 C24.1@4058.41,4468.49
  Bottom Layer w10: v3(5972.97,4033.49) 5974.12,4032.34 v3(5974.12,3951.49)
  Bottom Layer w20: CN7.2@3612.1,3127.03 3618.89,3133.82 3672.76,3133.82 3706.81,3167.87 3706.81,3297.9 3667.92,3336.78 D3.1@3667.92,3365.07 3667.92,3370.92 3732.24,3435.24 3732.24,3606.76 3766.16,3640.67 3860.95,3640.67 3961.87,3741.59 3961.87,4264.54 v4(4058.75,4361.43) ; v4(4883.12,4228.41) 4883.12,4016.51 v4(4885.6,4014.04) 4885.6,3745.66 v4(4900.59,3730.66) ; v4(6145.97,3980.49) 6145.97,4210.49 6356.97,4421.49 6356.97,4628.49 6259.07,4726.39 J7.2@6252.93,4726.39
EGND: C20.2 CN6.13 CN6.14 CN6.15 CN6.16 R34.1 | length 819.9
  Top Layer w20: CN6.14@3244.82,5821.52 CN6.16@3244.82,5986.12 CN6.15@3585.02,5986.12 CN6.13@3585.02,5821.52
  Bottom Layer w20: CN6.13@3585.02,5821.52 3586.88,5823.38 C20.2@3663.92,5823.38 R34.1@3663.92,5894.16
